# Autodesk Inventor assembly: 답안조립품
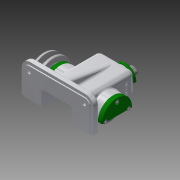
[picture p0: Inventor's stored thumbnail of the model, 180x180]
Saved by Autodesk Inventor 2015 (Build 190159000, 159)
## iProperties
Created: 2016-02
Part Number: 답안조립품
Document SubType Name: Assembly
Designer: Administrator
Author: Administrator
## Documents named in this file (19)
- C:\Users\Administrator\Desktop\460219V1004\답안조립품.iam
- C:\Users\Administrator\Desktop\460219V1004\V-벨트풀리.ipt
- C:\Users\Administrator\Desktop\460219V1004\고정핀.ipt
- C:\Users\Administrator\Desktop\460219V1004\뒤커버.ipt
- C:\Users\Administrator\Desktop\460219V1004\링크.ipt
- C:\Users\Administrator\Desktop\460219V1004\멈춤링 6 x 5.ipt
- C:\Users\Administrator\Desktop\460219V1004\멈춤링 15 x 1.ipt
- C:\Users\Administrator\Desktop\460219V1004\베어링 15 x 35 x 11.ipt
- C:\Users\Administrator\Desktop\460219V1004\본체.ipt
- C:\Users\Administrator\Desktop\460219V1004\볼트 M3 x 8.ipt
- C:\Users\Administrator\Desktop\460219V1004\볼트 M4 x 10.ipt
- C:\Users\Administrator\Desktop\460219V1004\볼트 M6 x 12.ipt
- C:\Users\Administrator\Desktop\460219V1004\상부부시.ipt
- C:\Users\Administrator\Desktop\460219V1004\슬라이드바.ipt
- C:\Users\Administrator\Desktop\460219V1004\앞커버.ipt
- C:\Users\Administrator\Desktop\460219V1004\오일실 15 25 7.ipt
- C:\Users\Administrator\Desktop\460219V1004\와셔.ipt
- C:\Users\Administrator\Desktop\460219V1004\키 5 x 5 x 14.ipt
- C:\Users\Administrator\Desktop\460219V1004\편심축.ipt
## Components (15 placed, 5 different names)
1. V-벨트풀리:1
2. 고정핀:1 — 플러쉬:2
3. ISO 4018 M6 x 12:1
4. ISO 4762 M4 x 10:2
5. ISO 4762 M4 x 10:3
6. ISO 4762 M4 x 10:4
7. ISO 4762 M4 x 10:5
8. ISO 4762 M3 x 8:1
9. ISO 4762 M3 x 8:2
10. ISO 4762 M3 x 8:3
11. ISO 4762 M3 x 8:4
12. ISO 4762 M4 x 10:1
13. ISO 4762 M4 x 10:6
14. ISO 4762 M4 x 10:7
15. ISO 4762 M4 x 10:8
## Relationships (1: Flush 1)
- 플러쉬:2 [Flush]: 고정핀:1
